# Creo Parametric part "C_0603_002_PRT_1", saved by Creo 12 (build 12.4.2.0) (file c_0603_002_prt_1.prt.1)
Units: Custom; MM, KILOGRAM, SECS

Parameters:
  PTC_WM_ITERATION = "0"
  PTC_WM_VERSION = "-.0"
  PTC_WM_LIFECYCLE_STATE = "In Work"
  PTC_WM_LIFECYCLE = "MO_CADDocument"
  PTC_WM_CREATED_BY = "Maximilian Roepper (Z0017RMS: MO)"
  PTC_WM_CREATED_ON = "18-Sep-26 11:36:42 AM"
  PTC_WM_MODIFIED_BY = "Maximilian Roepper (Z0017RMS: MO)"
  PTC_WM_MODIFIED_ON = "18-Sep-26 11:36:46 AM"
  PDMLINKNUMBER = "PDM000071454818"
  PTC_WM_NAME = "c_0603_002_prt_1.prt"
  PTC_WM_NUMBER = "PDM000071454818"

Other parameters: WEIGHT, WEIGHT_FACTOR, WEIGHT_ADD, _MASS_TEMP, _DIFF_TEMP, MC_ERRORS, SUPPLIER

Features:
  1. coordinate system
  2. datum plane "PRT_YZ"
  3. datum plane "PRT_XY"
  4. datum plane "PRT_XZ"
  5. coordinate system
  6. datum axis
  7. datum axis
  8. datum axis
  9. coordinate system
  10. imported feature
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
Other named items: PRT, SIEMENS_MO, DRW_VIEW_ORG, PRT_X, PRT_Y, PRT_Z, CS0, ROUGH_GROB

Layers: 00_STD_CSYS-KSYS, 01_STD_PLANES-EBENEN, 02_STD_AXES-ACHSEN, 03_STD_CSYS-KSYS, 24_IMPORT_FEAT-IMPORT_KE

Surfaces: 16 plane, 12 cylinder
